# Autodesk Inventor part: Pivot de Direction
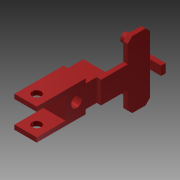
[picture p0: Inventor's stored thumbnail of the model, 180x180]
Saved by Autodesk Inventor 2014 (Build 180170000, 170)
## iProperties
Created: 2015-09
Part Number: Pivot de Direction
Material: Générique
Document SubType Name: Modeling
Designer: OL
Density: 1 g/cm^3
Appearance: Par défaut
Author: OL
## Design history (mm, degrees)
sketch "Esquisse1"
  geometry: L1 (-90, 35)-(20, 35); L2 (20, -35)-(-90, -35); L3 (-90, 25)-(-25, 25); L4 (-25, 25)-(-25, -25); L5 (-25, -25)-(-90, -25); L6 (-90, -35)-(-90, -25); L7 (-90, 25)-(-90, 35); L8 (20, 25)-(65, 25); L9 (65, 25)-(65, -25); L10 (65, -25)-(20, -25); L11 (20, 35)-(20, 25); L12 (20, -25)-(20, -35); C1 r 12.5 at (0, 0); 1 further point
  constraints: 24 end point, 7 parallel, 4 perpendicular, 3 horizontal, 1 centre point
  dimensions: "d2" = 70 distance of L2.end L1.start; "d3" = 65 distance from line of L2.end L4; "d4" = 35 distance from line of point (0, 0) L2; "d6" = 110 distance of L1.start L1.end; "d7" = 65 distance of L3.start L3.end; "d8" = 90 distance from line of L6 C1.centre; "d9" = 25 diameter of C1; "d10" = 155 distance between parallel lines of L9 L6; "d11" = 0 distance of point (0, 0) C1.centre; "d12" = 0 distance of point (0, 0) C1.centre; "d15" = 110 distance of L2.start L2.end; "d16" = 50 distance between parallel lines of L10 L8; "d17" = 25 distance from line of C1.centre L8; "d18" = 10 distance between parallel lines of L1 L3; "d19" = 10 distance between parallel lines of L2 L5
extrude "Extrusion1" new body sketch "Esquisse1" distance "d20" = 50; taper "d21" = 0 deg
sketch "Esquisse2"
  geometry: L1 (25, 65)-(-25, 65) reference; L2 (-25, 65)-(-25, 20) reference; L3 (-25, 45)-(25, 45); L4 (25, 45)-(25, 105); L5 (-25, 105)-(-25, 45); L6 (-65, 155)-(65, 155); L7 (75, 145)-(75, 115); L8 (-75, 115)-(-75, 145); L9 (65, 105)-(25, 105); L10 (-25, 105)-(-65, 105); L11 (-75, 145)-(-65, 155); L12 (-75, 115)-(-65, 105); L13 (65, 105)-(75, 115); L14 (75, 145)-(65, 155); C1 r 12.5 at (0, 0) reference; 1 further point
  constraints: 24 end point, 5 perpendicular, 4 parallel, 2 horizontal, 1 point on line
  dimensions: "d22" = 245 distance from line of L6 point (-25, -90); "d23" = 150 distance between parallel lines of L7 L8; "d24" = 50 distance between parallel lines of L6 L10; "d25" = 50 distance between parallel lines of L9 L6; "d26" = 10 horizontal distance of L7.start L6.end; "d27" = 10 horizontal distance of L7.start L6.end; "d28" = 10 horizontal distance of L9.start L7.end; "d29" = 10 horizontal distance of L8.start L10.end; "d30" = 10 horizontal distance of L8.end L6.start; "d31" = 75 distance from line of C1.centre L7; "d32" = 50 distance between parallel lines of L4 L5; "d33" = 20 distance between parallel lines of L1 L3
extrude "Extrusion2" join sketch "Esquisse2" distance "d34" = 10; taper "d35" = 0 deg
sketch "Esquisse3"
  geometry: L1 (0, 130)-(0, 0) reference; L2 (10, 130)-(10, 0) reference; L3 (0, 75)-(35, 75); L4 (35, 75)-(35, 55); L5 (35, 55)-(0, 55); L6 (0, 55)-(0, 75); L7 (0, -10)-(10, -10) reference; L8 (0, 140)-(10, 140) reference; 1 further point
  constraints: 8 end point, 2 parallel, 1 horizontal, 1 perpendicular, 1 point on line
  dimensions: "d36" = 65 distance between parallel lines of L7 L5; "d37" = 65 distance between parallel lines of L8 L3; "d38" = 25 distance between parallel lines of L2 L4
extrude "Extrusion3" join sketch "Esquisse3" distance "d39" = 10; taper "d40" = 0 deg
sketch "Esquisse4"
  geometry: L1 (65, 105)-(25, 105) reference; L2 (75, 145)-(75, 115) reference; L3 (-75, 115)-(-75, 145) reference; L4 (-25, 105)-(-65, 105) reference; C1 r 10 at (-50, 130); C2 r 10 at (50, 130); 1 further point
  constraints: 2 centre point
  dimensions: "d41" = 20 diameter of C1; "d43" = 20 diameter of C2; "d44" = 25 distance from line of L3 C1.centre; "d45" = 25 distance from line of L4 C1.centre; "d46" = 25 distance from line of L2 C2.centre; "d47" = 25 distance from line of L1 C2.centre
extrude "Extrusion4" join sketch "Esquisse4" distance "d48" = 23; taper "d49" = 0 deg
sketch "Esquisse5"
  geometry: L1 (-50, 0)-(-50, 110) reference; L2 (0, 0)-(-50, 0) reference; C1 r 10 at (-25, 25); 1 further point
  constraints: 1 centre point
  dimensions: "d50" = 20 diameter of C1; "d52" = 25 distance from line of L1 C1.centre; "d53" = 25 distance from line of L2 C1.centre
extrude "Extrusion5" cut sketch "Esquisse5" stored distance "d54" = 70; taper "d55" = 0 deg
sketch "Esquisse6"
  geometry: L1 (0, 0)-(0, -55) reference; L2 (-23, -5)-(-23, -25) reference; L3 (0, -25)-(0, -5) reference; L4 (-23, -105)-(-23, -125) reference; L5 (0, -125)-(0, -105) reference; C1 r 2.5 at (-15.5, -15); C2 r 2.5 at (-15.5, -115); 1 further point
  constraints: 2 centre point
  dimensions: "d56" = 5 diameter of C1; "d58" = 5 diameter of C2; "d59" = 15.5 distance from line of L1 C1.centre; "d60" = 15.5 distance from line of L5 C2.centre; "d61" = 10 vertical distance of L4.end C2.centre; "d62" = 10 vertical distance of L2.start C1.centre
extrude "Extrusion6" cut sketch "Esquisse6" distance "d63" = 40; taper "d64" = 0 deg
chamfer "Chanfrein1" distance "d65" = 1; stored, may be unused: second distance "d66" = 2, angle "d67" = 45 deg
node "Solide1"
node "Boucle projetée1"
node "Boucle projetée2"
